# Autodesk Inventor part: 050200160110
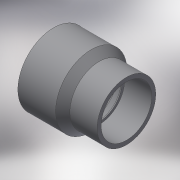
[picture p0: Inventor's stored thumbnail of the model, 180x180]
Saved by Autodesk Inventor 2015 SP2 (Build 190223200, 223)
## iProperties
Created: 2017-10
Part Number: 050200160110
Material: Generic
Description: PLASSON REDUCING SOCKET M.F.160(140)110 CEMENTED
Document SubType Name: Modeling
Designer: KIM
Density: 1 g/cm^3
Appearance: Default
Author: KIM
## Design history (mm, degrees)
derived "050200.ipt"
feature "Solid1::050200.ipt"
tag "TaggingFeature1"
body "Solid1"
other parameters: "d0" = 157, "d1" = 86, "d2" = 61, "d3" = 76, "d8" = 99, "d9" = 9.82794, "d12" = 1.4, "L_" = 86, "l_" = 76, "l_1" = 61, "H_" = 157, "d11" = 9.82794
